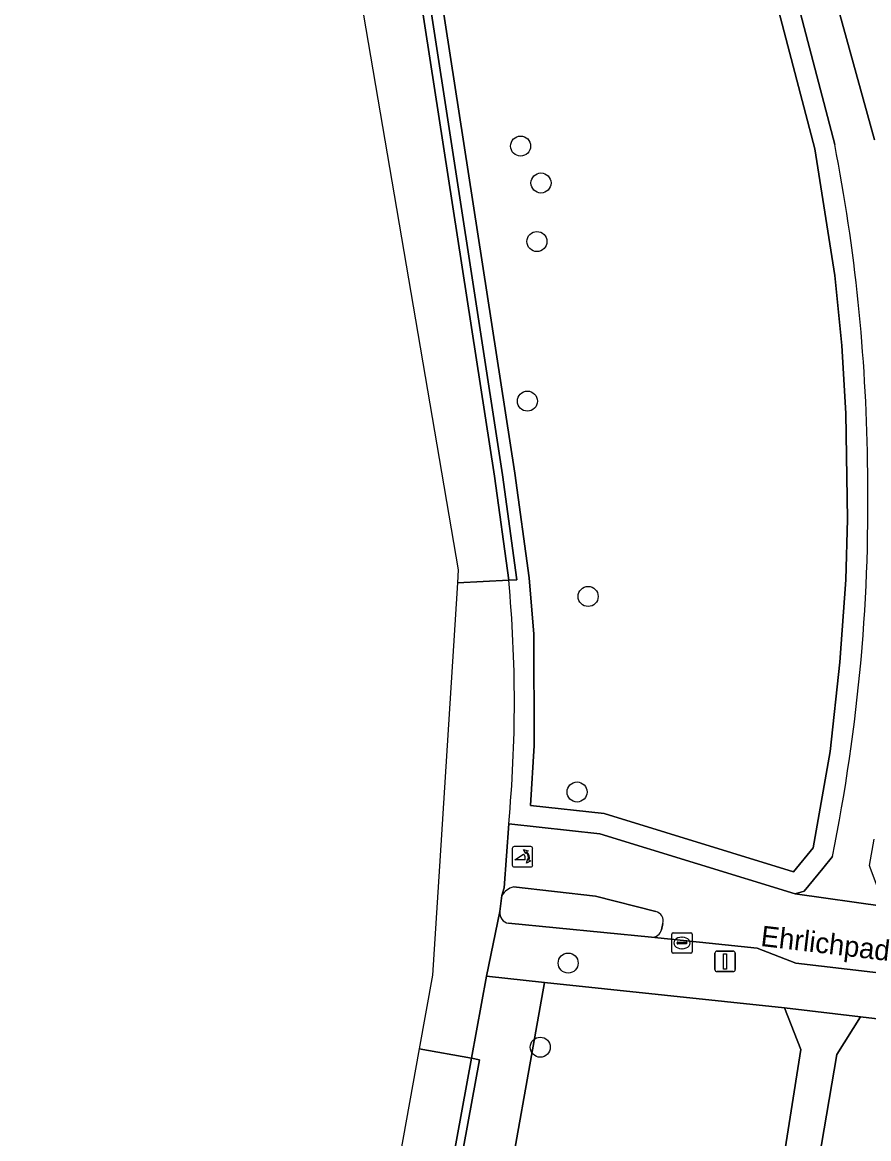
# Model space of a CAD drawing. Extents: x 162156 to 163172, y 378995 to 380779.
# Drawn here: x 162215.9 to 162257.2, y 380486.8 to 380541.3 of the extents above; entities that cross this region are included whole.
import ezdxf

# ---------------------------------------------------------------- set-up
doc = ezdxf.new("R2010")
doc.units = 0
for name, color, linetype in [('IMGEO_Berm_open', 7, 'Continuous'), ('IMGEO_Boom', 7, 'Continuous'), ('IMGEO_Fietspad_open', 7, 'Continuous'), ('IMGEO_Gemengd_bos', 7, 'Continuous'), ('IMGEO_Groenvoorziening', 7, 'Continuous'), ('IMGEO_Kolk', 7, 'Continuous'), ('IMGEO_Lichtmast', 7, 'Continuous'), ('IMGEO_Loofbos', 7, 'Continuous'), ('IMGEO_Openbare_ruimte_label', 7, 'Continuous'), ('IMGEO_Poller', 7, 'Continuous'), ('IMGEO_Rijbaan_lokaal_gesloten', 7, 'Continuous'), ('IMGEO_Rijbaan_lokaal_open', 7, 'Continuous'), ('IMGEO_Verkeerseiland_gesloten', 7, 'Continuous'), ('IMGEO_Voetpad_halfverhard', 7, 'Continuous'), ('IMGEO_Voetpad_open', 7, 'Continuous')]:
    doc.layers.add(name, color=color, linetype=linetype)

msp = doc.modelspace()

# ---------------------------------------------------------------- linework, layer by layer
at = {"layer": 'IMGEO_Berm_open'}
for points in [[(162235.365, 380542.497), (162238.975, 380519.141), (162239.667, 380514.065), (162240.067, 380514.084), (162239.371, 380519.199), (162235.761, 380542.553)], [(162234.465, 380470.084), (162238.243, 380490.669), (162237.85, 380490.741), (162234.069, 380470.13), (162223.611, 380413.114)]]:
    msp.add_lwpolyline(points, dxfattribs=at)
at = {"layer": 'IMGEO_Boom'}
for centre in [(162240.248, 380535.245), (162241.242, 380533.444), (162241.045, 380530.587), (162240.578, 380522.802), (162243.543, 380513.272), (162243.002, 380503.731), (162242.569, 380495.387), (162241.208, 380491.28)]:
    msp.add_circle(centre, 0.489, dxfattribs=at)
at = {"layer": 'IMGEO_Fietspad_open'}
for points in [[(162258.032, 380498.149), (162253.643, 380498.76), (162244.114, 380501.695), (162239.667, 380502.183), (162239.443, 380499.049), (162239.331, 380498.681)], [(162239.897, 380499.1), (162243.898, 380498.65), (162246.842, 380497.908)], [(162247.193, 380497.313), (162247.117, 380497.011)], [(162246.64, 380496.651), (162251.799, 380496.107), (162253.679, 380495.374), (162261.479, 380494.463), (162276.052, 380492.752), (162279.27, 380492.322)]]:
    msp.add_lwpolyline(points, dxfattribs=at)
for centre, radius, start, end in [((162240.159, 380498.155), 0.981, 105.4674, 147.5564), ((162246.727, 380497.439), 0.483, 344.8687, 76.2054), ((162246.668, 380497.11), 0.46, 266.5198, 347.5651)]:
    msp.add_arc(centre, radius, start, end, dxfattribs=at)
at = {"layer": 'IMGEO_Gemengd_bos'}
for points in [[(162241.421, 380494.439), (162237.021, 380469.785)], [(162253.128, 380493.195), (162241.421, 380494.439)], [(162249.406, 380393.789), (162249.207, 380401.688), (162246.926, 380442.121), (162248.241, 380458.763), (162252.833, 380484.254), (162253.931, 380491.166), (162253.128, 380493.195)]]:
    msp.add_lwpolyline(points, dxfattribs=at)
at = {"layer": 'IMGEO_Groenvoorziening'}
for points in [[(162255.579, 380535.316), (162252.497, 380547.125), (162251.296, 380555.302), (162251.308, 380571.991), (162251.815, 380588.717), (162253.726, 380612.608), (162254.214, 380621.511), (162254.598, 380636.43), (162249.583, 380637.106), (162241.841, 380637.822)], [(162287.548, 380617.667), (162278.42, 380615.932), (162268.567, 380615.161), (162259.146, 380615.166), (162255.478, 380612.381), (162253.846, 380590.319), (162253.137, 380572.056), (162253.239, 380555.266), (162254.236, 380547.456), (162257.522, 380535.546)], [(162251.516, 380546.925), (162254.601, 380535.104), (162255.589, 380528.927), (162255.924, 380525.512), (162256.12, 380522.192), (162256.204, 380517.049), (162256.127, 380514.082), (162255.833, 380510.065), (162255.36, 380505.712), (162254.529, 380501.011), (162253.566, 380499.83), (162244.318, 380502.678), (162240.725, 380503.073), (162240.909, 380506.002), (162240.892, 380511.437), (162240.661, 380514.175), (162239.965, 380519.285), (162236.355, 380542.643)], [(162235.761, 380542.553), (162239.371, 380519.199), (162240.067, 380514.084), (162239.667, 380514.065)], [(162239.667, 380502.183), (162244.114, 380501.695), (162253.643, 380498.76), (162254.088, 380498.889), (162254.994, 380500), (162255.468, 380500.581)], [(162277.755, 380490.274), (162256.84, 380492.77), (162255.685, 380490.93), (162250.184, 380458.654)]]:
    msp.add_lwpolyline(points, dxfattribs=at)
msp.add_lwpolyline([(162241.421, 380494.439), (162238.578, 380494.742), (162237.85, 380490.741), (162238.243, 380490.669), (162234.465, 380470.084), (162237.021, 380469.785)], close=True, dxfattribs=at)
for centre, radius, start, end in [((162170.498, 380518.698), 86.689, 0.76898, 11.05216), ((162170.31, 380517.854), 86.892, 348.53381, 1.32336), ((162176.095, 380508.124), 63.849, 354.66102, 5.33898)]:
    msp.add_arc(centre, radius, start, end, dxfattribs=at)
at = {"layer": 'IMGEO_Kolk'}
for p, q in [((162247.624, 380495.94), (162247.624, 380496.792)), ((162247.699, 380496.866), (162248.551, 380496.866)), ((162248.112, 380496.646), (162248.137, 380496.646)), ((162248.625, 380496.792), (162248.625, 380495.94)), ((162247.883, 380496.36), (162247.883, 380496.372)), ((162248.321, 380496.323), (162247.923, 380496.323)), ((162247.926, 380496.409), (162248.324, 380496.409)), ((162248.367, 380496.372), (162248.367, 380496.36)), ((162248.551, 380495.866), (162247.699, 380495.866)), ((162248.135, 380496.086), (162248.11, 380496.086))]:
    msp.add_line(p, q, dxfattribs=at)
for points in [[(162247.624, 380495.94), (162247.624, 380496.792)], [(162247.699, 380496.866), (162248.551, 380496.866)], [(162248.625, 380496.792), (162248.625, 380495.94)], [(162248.551, 380495.866), (162247.699, 380495.866)]]:
    msp.add_lwpolyline(points, dxfattribs=at)
for centre, radius, start, end in [((162247.701, 380496.79), 0.0765, 91.552, 178.448), ((162247.701, 380496.79), 0.0765, 91.552, 178.448), ((162248.549, 380496.79), 0.0765, 1.552, 88.448), ((162248.549, 380496.79), 0.0765, 1.552, 88.448), ((162247.923, 380496.369), 0.0403, 85.8775, 175.7526), ((162247.92, 380496.359), 0.0366, 178.938, 274.7102), ((162248.324, 380496.366), 0.043, 264.8664, 352.4533), ((162248.328, 380496.371), 0.0386, 1.7309, 96.639), ((162247.701, 380495.942), 0.0765, 181.552, 268.448), ((162247.701, 380495.942), 0.0765, 181.552, 268.448), ((162248.549, 380495.942), 0.0765, 271.552, 358.448), ((162248.549, 380495.942), 0.0765, 271.552, 358.448)]:
    msp.add_arc(centre, radius, start, end, dxfattribs=at)
for centre, major_axis, ratio, start_param, end_param in [((162248.111, 380496.366), (-0.387, 0.002), 0.722429, 4.712389, 7.853982), ((162248.136, 380496.366), (-0.39, 0.002), 0.717154, 1.570796, 4.712389)]:
    msp.add_ellipse(centre, major_axis=major_axis, ratio=ratio, start_param=start_param, end_param=end_param, dxfattribs=at)
at = {"layer": 'IMGEO_Lichtmast'}
for p, q in [((162249.733, 380495.068), (162249.733, 380495.868)), ((162249.733, 380495.868), (162249.733, 380495.068)), ((162249.833, 380495.968), (162250.623, 380495.968)), ((162250.623, 380495.968), (162249.833, 380495.968)), ((162250.723, 380495.868), (162250.723, 380495.068)), ((162250.723, 380495.068), (162250.723, 380495.868)), ((162250.623, 380494.968), (162249.833, 380494.968)), ((162249.833, 380494.968), (162250.623, 380494.968))]:
    msp.add_line(p, q, dxfattribs=at)
msp.add_lwpolyline([(162250.153, 380495.843), (162250.303, 380495.843), (162250.303, 380495.093), (162250.153, 380495.093), (162250.153, 380495.843)], dxfattribs=at)
for centre, start, end in [((162249.833, 380495.868), 90, 180), ((162249.833, 380495.868), 90, 180), ((162250.623, 380495.868), 0, 90), ((162250.623, 380495.868), 360, 90), ((162249.833, 380495.068), 180, 270), ((162249.833, 380495.068), 180, 270), ((162250.623, 380495.068), 270, 0), ((162250.623, 380495.068), 270, 0)]:
    msp.add_arc(centre, 0.1, start, end, dxfattribs=at)
at = {"layer": 'IMGEO_Loofbos'}
msp.add_lwpolyline([(162236.355, 380542.643), (162239.965, 380519.285), (162240.661, 380514.175), (162240.892, 380511.437), (162240.909, 380506.002), (162240.725, 380503.073), (162244.318, 380502.678), (162253.566, 380499.83), (162254.529, 380501.011), (162255.36, 380505.712), (162255.833, 380510.065), (162256.127, 380514.082), (162256.204, 380517.049), (162256.12, 380522.192), (162255.924, 380525.512), (162255.589, 380528.927), (162254.601, 380535.104), (162251.516, 380546.925)], dxfattribs=at)
at = {"layer": 'IMGEO_Poller'}
for p, q in [((162240.742, 380501.072), (162239.934, 380501.072)), ((162240.742, 380501.072), (162239.934, 380501.072)), ((162239.84, 380500.977), (162239.84, 380500.17)), ((162239.84, 380500.977), (162239.84, 380500.17)), ((162240.836, 380500.17), (162240.836, 380500.977)), ((162240.836, 380500.17), (162240.836, 380500.977)), ((162239.934, 380500.075), (162240.742, 380500.075)), ((162239.934, 380500.075), (162240.742, 380500.075))]:
    msp.add_line(p, q, dxfattribs=at)
for points in [[(162240.475, 380500.428), (162239.962, 380500.428), (162240.392, 380500.703)], [(162240.519, 380500.801), (162240.507, 380500.728), (162240.382, 380500.933)], [(162240.382, 380500.933), (162240.613, 380500.867), (162240.542, 380500.835)], [(162240.535, 380500.256), (162240.601, 380500.487), (162240.631, 380500.419)], [(162240.667, 380500.392), (162240.739, 380500.381), (162240.535, 380500.256)]]:
    msp.add_lwpolyline(points, dxfattribs=at)
for centre, radius, start, end in [((162239.934, 380500.977), 0.0946, 90, 180), ((162239.934, 380500.977), 0.0946, 90, 180), ((162240.742, 380500.977), 0.0946, 0, 90), ((162240.742, 380500.977), 0.0946, 0, 90), ((162240.147, 380500.478), 0.332, 351.3247, 42.4854), ((162240.161, 380500.488), 0.476, 351.7527, 41.1691), ((162240.161, 380500.488), 0.516, 349.3569, 42.2912), ((162239.934, 380500.17), 0.0946, 180, 270), ((162239.934, 380500.17), 0.0946, 180, 270), ((162240.742, 380500.17), 0.0946, 270, 0), ((162240.742, 380500.17), 0.0946, 270, 0)]:
    msp.add_arc(centre, radius, start, end, dxfattribs=at)
at = {"layer": 'IMGEO_Rijbaan_lokaal_gesloten'}
for points in [[(162236.98, 380632.149), (162231.316, 380576.014), (162231.316, 380549.081), (162237.206, 380514.575), (162237.166, 380513.944), (162237.166, 380513.944), (162239.667, 380514.065), (162238.975, 380519.141), (162235.365, 380542.497)], [(162223.611, 380413.114), (162234.069, 380470.13), (162237.85, 380490.741), (162235.298, 380491.209), (162235.298, 380491.209), (162222.121, 380418.077), (162217.494, 380387.779), (162215.927, 380369.051)]]:
    msp.add_lwpolyline(points, dxfattribs=at)
at = {"layer": 'IMGEO_Rijbaan_lokaal_open'}
for points in [[(162239.667, 380514.065), (162237.166, 380513.944), (162237.166, 380513.944), (162236.283, 380500.112), (162235.944, 380494.797), (162235.298, 380491.209)], [(162235.298, 380491.209), (162235.298, 380491.209), (162237.85, 380490.741), (162238.578, 380494.742), (162239.235, 380497.897), (162239.331, 380498.681), (162239.443, 380499.049), (162239.667, 380502.183)]]:
    msp.add_lwpolyline(points, dxfattribs=at)
msp.add_arc((162176.095, 380508.124), 63.849, 354.66102, 5.33898, dxfattribs=at)
at = {"layer": 'IMGEO_Verkeerseiland_gesloten'}
for points in [[(162246.842, 380497.908), (162243.898, 380498.65), (162239.897, 380499.1)], [(162239.331, 380498.681), (162239.235, 380497.897)], [(162239.656, 380497.325), (162246.64, 380496.651)], [(162247.117, 380497.011), (162247.193, 380497.313)]]:
    msp.add_lwpolyline(points, dxfattribs=at)
for centre, radius, start, end in [((162240.159, 380498.155), 0.981, 105.4674, 147.5564), ((162239.742, 380497.829), 0.511, 172.3729, 260.3343), ((162246.727, 380497.439), 0.483, 344.8687, 76.2054), ((162246.668, 380497.11), 0.46, 266.5198, 347.5651)]:
    msp.add_arc(centre, radius, start, end, dxfattribs=at)
at = {"layer": 'IMGEO_Voetpad_halfverhard'}
for points in [[(162254.236, 380547.456), (162253.239, 380555.266), (162253.137, 380572.056), (162253.846, 380590.319), (162255.478, 380612.381), (162256.194, 380621.615), (162256.302, 380628.128), (162256.435, 380636.205), (162254.598, 380636.43), (162254.214, 380621.511), (162253.726, 380612.608), (162251.815, 380588.717), (162251.308, 380571.991), (162251.296, 380555.302), (162252.497, 380547.125), (162255.579, 380535.316)], [(162257.522, 380535.546), (162254.236, 380547.456)], [(162255.468, 380500.581), (162254.994, 380500), (162254.088, 380498.889), (162253.643, 380498.76), (162258.032, 380498.149), (162257.33, 380500), (162257.271, 380500.139), (162257.509, 380501.429)], [(162250.184, 380458.654), (162255.685, 380490.93), (162256.84, 380492.77), (162253.128, 380493.195), (162253.931, 380491.166), (162252.833, 380484.254), (162248.241, 380458.763), (162246.926, 380442.121), (162249.207, 380401.688), (162249.406, 380393.789)]]:
    msp.add_lwpolyline(points, dxfattribs=at)
for centre, radius, start, end in [((162170.498, 380518.698), 86.689, 0.76898, 11.05216), ((162170.31, 380517.854), 86.892, 348.53381, 1.32336)]:
    msp.add_arc(centre, radius, start, end, dxfattribs=at)
at = {"layer": 'IMGEO_Voetpad_open'}
for points in [[(162239.235, 380497.897), (162238.578, 380494.742), (162241.421, 380494.439), (162253.128, 380493.195), (162256.84, 380492.77), (162277.755, 380490.274)], [(162279.27, 380492.322), (162276.052, 380492.752), (162261.479, 380494.463), (162253.679, 380495.374), (162251.799, 380496.107), (162246.64, 380496.651), (162239.656, 380497.325)]]:
    msp.add_lwpolyline(points, dxfattribs=at)
msp.add_arc((162239.742, 380497.829), 0.511, 172.3729, 260.3343, dxfattribs=at)

# ---------------------------------------------------------------- texts
at = {"layer": 'IMGEO_Openbare_ruimte_label'}
msp.add_text('Ehrlichpad', height=1, rotation=353.2801, dxfattribs=at).set_placement((162251.931, 380496.224))

doc.saveas('drawing.dxf')
